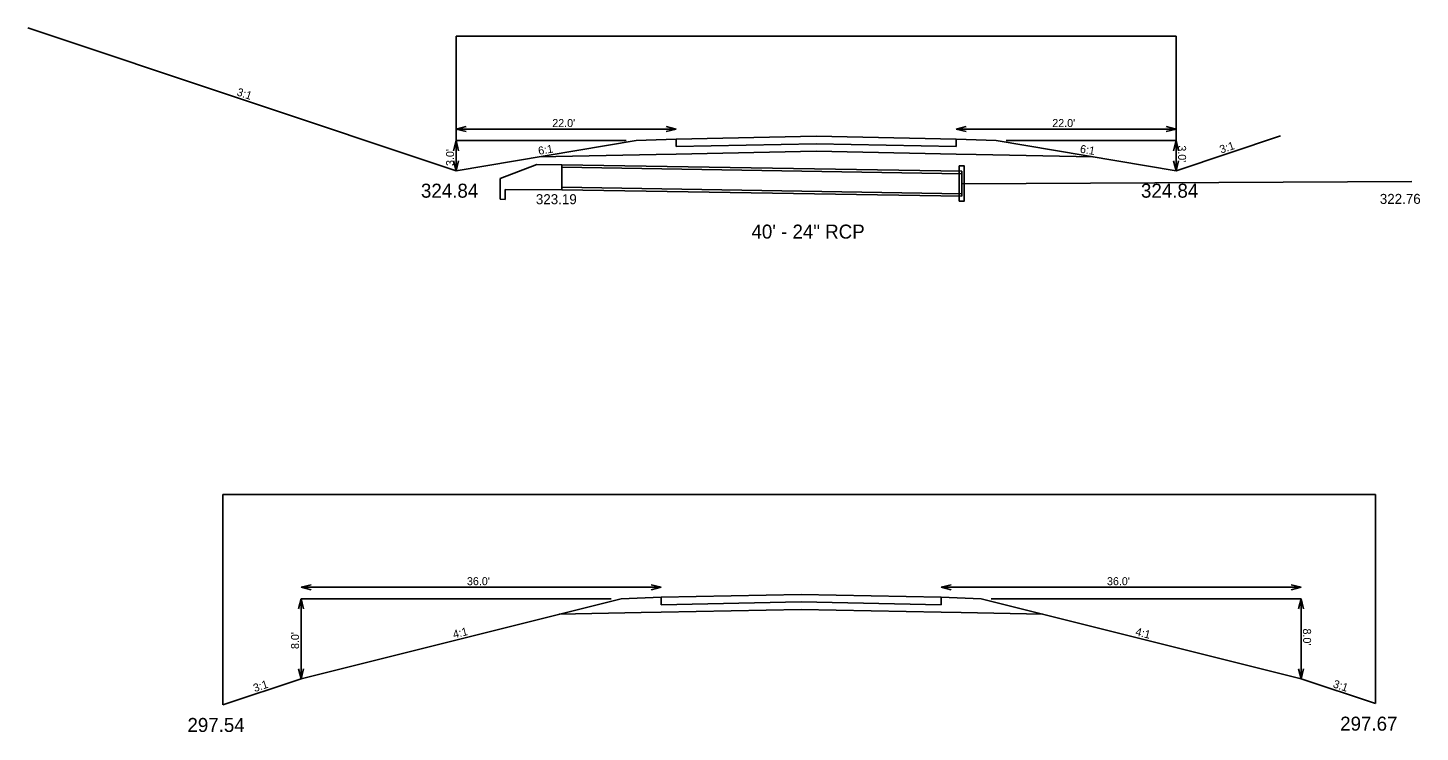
# Model space of a CAD drawing. Extents: x 2432865 to 2441203, y 1814550 to 1826842.
# Drawn here: x 2441063.6 to 2441202.8, y 1815393.3 to 1815463.7 of the extents above; entities that cross this region are included whole.
import ezdxf

# ---------------------------------------------------------------- set-up
doc = ezdxf.new("R2010")
doc.units = 0
for name, color, linetype in [('Default', 7, 'Continuous'), ('X_DRAINAGE_PIPES', 7, 'Continuous'), ('XS_M_DITCH', 7, 'Continuous'), ('XS_P_DRAINAGE', 7, 'Continuous'), ('XS_P_FINISHED_GRADE', 7, 'Continuous'), ('XS_P_SUBGRADE_GRANULAR', 7, 'Continuous'), ('XS_P_SUBGRADE_PAVEMENT', 7, 'Continuous'), ('XS_P_TX_CLEARZONE', 7, 'Continuous'), ('XS_P_TX_DCH', 7, 'Continuous'), ('XS_P_TX_FS_BS', 7, 'Continuous')]:
    doc.layers.add(name, color=color, linetype=linetype)

msp = doc.modelspace()

# ---------------------------------------------------------------- linework, layer by layer
at = {"layer": 'X_DRAINAGE_PIPES'}
msp.add_line((2441201.95, 1815448.31), (2441156.93, 1815448.09), dxfattribs=at)
at = {"layer": 'XS_M_DITCH'}
for p, q in [((2441106.37, 1815449.39), (2441106.37, 1815462.83)), ((2441106.37, 1815462.83), (2441178.37, 1815462.83)), ((2441106.37, 1815449.39), (2441106.37, 1815462.83)), ((2441106.37, 1815462.83), (2441178.37, 1815462.83)), ((2441178.37, 1815462.83), (2441178.37, 1815449.39)), ((2441178.37, 1815462.83), (2441178.37, 1815449.39)), ((2441083.04, 1815395.99), (2441083.04, 1815417.04)), ((2441083.04, 1815417.04), (2441198.3, 1815417.04)), ((2441083.04, 1815395.99), (2441083.04, 1815417.04)), ((2441083.04, 1815417.04), (2441198.3, 1815417.04)), ((2441198.3, 1815417.04), (2441198.3, 1815396.12)), ((2441198.3, 1815417.04), (2441198.3, 1815396.12))]:
    msp.add_line(p, q, dxfattribs=at)
at = {"layer": 'XS_P_DRAINAGE'}
for p, q in [((2441110.78, 1815448.61), (2441114.45, 1815450.01)), ((2441114.45, 1815450.01), (2441116.95, 1815449.99)), ((2441116.95, 1815449.99), (2441116.94, 1815447.49)), ((2441116.95, 1815449.99), (2441116.94, 1815447.49)), ((2441116.95, 1815449.99), (2441156.95, 1815449.34)), ((2441116.95, 1815449.74), (2441156.94, 1815449.09)), ((2441156.95, 1815449.34), (2441156.94, 1815446.84)), ((2441110.77, 1815446.53), (2441110.78, 1815448.61)), ((2441116.94, 1815447.74), (2441156.94, 1815447.09)), ((2441111.27, 1815446.52), (2441110.77, 1815446.53)), ((2441116.94, 1815447.49), (2441111.27, 1815447.52)), ((2441111.27, 1815447.52), (2441111.27, 1815446.52)), ((2441116.94, 1815447.49), (2441156.94, 1815446.84))]:
    msp.add_line(p, q, dxfattribs=at)
msp.add_lwpolyline([(2441156.68, 1815449.86), (2441157.18, 1815449.86), (2441157.18, 1815446.35), (2441156.68, 1815446.35)], close=True, dxfattribs=at)
at = {"layer": 'XS_P_FINISHED_GRADE'}
for p, q in [((2441106.37, 1815449.39), (2441063.55, 1815463.66)), ((2441106.37, 1815449.39), (2441063.55, 1815463.66)), ((2441124.37, 1815452.39), (2441106.37, 1815449.39)), ((2441124.37, 1815452.39), (2441106.37, 1815449.39)), ((2441128.37, 1815452.55), (2441124.37, 1815452.39)), ((2441128.37, 1815452.55), (2441124.37, 1815452.39)), ((2441128.37, 1815452.55), (2441142.37, 1815452.83)), ((2441128.37, 1815452.55), (2441142.37, 1815452.83)), ((2441142.37, 1815452.83), (2441156.37, 1815452.55)), ((2441142.37, 1815452.83), (2441156.37, 1815452.55)), ((2441156.37, 1815452.55), (2441160.37, 1815452.39)), ((2441156.37, 1815452.55), (2441160.37, 1815452.39)), ((2441160.37, 1815452.39), (2441178.37, 1815449.39)), ((2441160.37, 1815452.39), (2441178.37, 1815449.39)), ((2441178.37, 1815449.39), (2441188.81, 1815452.87)), ((2441178.37, 1815449.39), (2441188.81, 1815452.87)), ((2441122.87, 1815406.6), (2441090.87, 1815398.6)), ((2441122.87, 1815406.6), (2441090.87, 1815398.6)), ((2441126.87, 1815406.76), (2441122.87, 1815406.6)), ((2441126.87, 1815406.76), (2441122.87, 1815406.6)), ((2441126.87, 1815406.76), (2441140.87, 1815407.04)), ((2441126.87, 1815406.76), (2441140.87, 1815407.04)), ((2441140.87, 1815407.04), (2441154.87, 1815406.76)), ((2441140.87, 1815407.04), (2441154.87, 1815406.76)), ((2441154.87, 1815406.76), (2441158.87, 1815406.6)), ((2441154.87, 1815406.76), (2441158.87, 1815406.6)), ((2441158.87, 1815406.6), (2441190.87, 1815398.6)), ((2441158.87, 1815406.6), (2441190.87, 1815398.6)), ((2441090.87, 1815398.6), (2441083.04, 1815395.99)), ((2441090.87, 1815398.6), (2441083.04, 1815395.99)), ((2441190.87, 1815398.6), (2441198.3, 1815396.12)), ((2441190.87, 1815398.6), (2441198.3, 1815396.12))]:
    msp.add_line(p, q, dxfattribs=at)
at = {"layer": 'XS_P_SUBGRADE_GRANULAR'}
for p, q in [((2441126.37, 1815451.01), (2441114.69, 1815450.78)), ((2441126.37, 1815451.01), (2441114.69, 1815450.78)), ((2441128.37, 1815451.05), (2441126.37, 1815451.01)), ((2441128.37, 1815451.05), (2441126.37, 1815451.01)), ((2441128.37, 1815451.05), (2441142.37, 1815451.33)), ((2441128.37, 1815451.05), (2441142.37, 1815451.33)), ((2441142.37, 1815451.33), (2441156.37, 1815451.05)), ((2441142.37, 1815451.33), (2441156.37, 1815451.05)), ((2441156.37, 1815451.05), (2441158.37, 1815451.01)), ((2441156.37, 1815451.05), (2441158.37, 1815451.01)), ((2441158.37, 1815451.01), (2441170.06, 1815450.78)), ((2441158.37, 1815451.01), (2441170.06, 1815450.78)), ((2441124.87, 1815405.22), (2441116.69, 1815405.06)), ((2441124.87, 1815405.22), (2441116.69, 1815405.06)), ((2441126.87, 1815405.26), (2441124.87, 1815405.22)), ((2441126.87, 1815405.26), (2441124.87, 1815405.22)), ((2441126.87, 1815405.26), (2441140.87, 1815405.54)), ((2441126.87, 1815405.26), (2441140.87, 1815405.54)), ((2441140.87, 1815405.54), (2441154.87, 1815405.26)), ((2441140.87, 1815405.54), (2441154.87, 1815405.26)), ((2441154.87, 1815405.26), (2441156.87, 1815405.22)), ((2441154.87, 1815405.26), (2441156.87, 1815405.22)), ((2441156.87, 1815405.22), (2441165.04, 1815405.06)), ((2441156.87, 1815405.22), (2441165.04, 1815405.06))]:
    msp.add_line(p, q, dxfattribs=at)
at = {"layer": 'XS_P_SUBGRADE_PAVEMENT'}
for p, q in [((2441128.37, 1815451.8), (2441128.37, 1815452.55)), ((2441128.37, 1815451.8), (2441128.37, 1815452.55)), ((2441128.37, 1815451.8), (2441142.37, 1815452.08)), ((2441128.37, 1815451.8), (2441142.37, 1815452.08)), ((2441142.37, 1815452.08), (2441156.37, 1815451.8)), ((2441142.37, 1815452.08), (2441156.37, 1815451.8)), ((2441156.37, 1815451.8), (2441156.37, 1815452.55)), ((2441156.37, 1815451.8), (2441156.37, 1815452.55)), ((2441126.87, 1815406.01), (2441126.87, 1815406.76)), ((2441126.87, 1815406.01), (2441126.87, 1815406.76)), ((2441126.87, 1815406.01), (2441140.87, 1815406.29)), ((2441126.87, 1815406.01), (2441140.87, 1815406.29)), ((2441140.87, 1815406.29), (2441154.87, 1815406.01)), ((2441140.87, 1815406.29), (2441154.87, 1815406.01)), ((2441154.87, 1815406.01), (2441154.87, 1815406.76)), ((2441154.87, 1815406.01), (2441154.87, 1815406.76))]:
    msp.add_line(p, q, dxfattribs=at)
at = {"layer": 'XS_P_TX_CLEARZONE'}
for p, q in [((2441106.37, 1815453.55), (2441107.37, 1815453.8)), ((2441106.37, 1815453.55), (2441107.37, 1815453.8)), ((2441106.37, 1815453.55), (2441107.37, 1815453.3)), ((2441128.37, 1815453.55), (2441106.37, 1815453.55)), ((2441106.37, 1815453.55), (2441107.37, 1815453.3)), ((2441128.37, 1815453.55), (2441106.37, 1815453.55)), ((2441128.37, 1815453.55), (2441127.37, 1815453.8)), ((2441128.37, 1815453.55), (2441127.37, 1815453.8)), ((2441128.37, 1815453.55), (2441127.37, 1815453.3)), ((2441128.37, 1815453.55), (2441127.37, 1815453.3)), ((2441156.37, 1815453.55), (2441157.37, 1815453.8)), ((2441156.37, 1815453.55), (2441157.37, 1815453.8)), ((2441156.37, 1815453.55), (2441157.37, 1815453.3)), ((2441156.37, 1815453.55), (2441178.37, 1815453.55)), ((2441156.37, 1815453.55), (2441157.37, 1815453.3)), ((2441156.37, 1815453.55), (2441178.37, 1815453.55)), ((2441178.37, 1815453.55), (2441177.37, 1815453.8)), ((2441178.37, 1815453.55), (2441177.37, 1815453.8)), ((2441178.37, 1815453.55), (2441177.37, 1815453.3)), ((2441178.37, 1815453.55), (2441177.37, 1815453.3)), ((2441106.37, 1815452.39), (2441106.12, 1815451.39)), ((2441106.37, 1815452.39), (2441106.12, 1815451.39)), ((2441106.37, 1815452.39), (2441106.62, 1815451.39)), ((2441106.37, 1815452.39), (2441106.37, 1815449.39)), ((2441123.37, 1815452.39), (2441106.37, 1815452.39)), ((2441106.37, 1815452.39), (2441106.62, 1815451.39)), ((2441106.37, 1815452.39), (2441106.37, 1815449.39)), ((2441123.37, 1815452.39), (2441106.37, 1815452.39)), ((2441161.37, 1815452.39), (2441178.37, 1815452.39)), ((2441161.37, 1815452.39), (2441178.37, 1815452.39)), ((2441178.37, 1815452.39), (2441178.12, 1815451.39)), ((2441178.37, 1815452.39), (2441178.12, 1815451.39)), ((2441178.37, 1815452.39), (2441178.37, 1815449.39)), ((2441178.37, 1815452.39), (2441178.62, 1815451.39)), ((2441178.37, 1815452.39), (2441178.37, 1815449.39)), ((2441178.37, 1815452.39), (2441178.62, 1815451.39)), ((2441106.37, 1815449.39), (2441106.12, 1815450.39)), ((2441106.37, 1815449.39), (2441106.12, 1815450.39)), ((2441106.37, 1815449.39), (2441106.62, 1815450.39)), ((2441106.37, 1815449.39), (2441106.62, 1815450.39)), ((2441178.37, 1815449.39), (2441178.12, 1815450.39)), ((2441178.37, 1815449.39), (2441178.12, 1815450.39)), ((2441178.37, 1815449.39), (2441178.62, 1815450.39)), ((2441178.37, 1815449.39), (2441178.62, 1815450.39)), ((2441090.87, 1815407.76), (2441091.87, 1815408.01)), ((2441090.87, 1815407.76), (2441091.87, 1815408.01)), ((2441090.87, 1815407.76), (2441091.87, 1815407.51)), ((2441126.87, 1815407.76), (2441090.87, 1815407.76)), ((2441090.87, 1815407.76), (2441091.87, 1815407.51)), ((2441126.87, 1815407.76), (2441090.87, 1815407.76)), ((2441126.87, 1815407.76), (2441125.87, 1815408.01)), ((2441126.87, 1815407.76), (2441125.87, 1815408.01)), ((2441126.87, 1815407.76), (2441125.87, 1815407.51)), ((2441126.87, 1815407.76), (2441125.87, 1815407.51)), ((2441154.87, 1815407.76), (2441155.87, 1815408.01)), ((2441154.87, 1815407.76), (2441155.87, 1815408.01)), ((2441154.87, 1815407.76), (2441155.87, 1815407.51)), ((2441154.87, 1815407.76), (2441190.87, 1815407.76)), ((2441154.87, 1815407.76), (2441155.87, 1815407.51)), ((2441154.87, 1815407.76), (2441190.87, 1815407.76)), ((2441190.87, 1815407.76), (2441189.87, 1815408.01)), ((2441190.87, 1815407.76), (2441189.87, 1815408.01)), ((2441190.87, 1815407.76), (2441189.87, 1815407.51)), ((2441190.87, 1815407.76), (2441189.87, 1815407.51)), ((2441090.87, 1815406.6), (2441090.62, 1815405.6)), ((2441090.87, 1815406.6), (2441090.62, 1815405.6)), ((2441090.87, 1815406.6), (2441091.12, 1815405.6)), ((2441090.87, 1815406.6), (2441090.87, 1815398.6)), ((2441121.87, 1815406.6), (2441090.87, 1815406.6)), ((2441090.87, 1815406.6), (2441091.12, 1815405.6)), ((2441090.87, 1815406.6), (2441090.87, 1815398.6)), ((2441121.87, 1815406.6), (2441090.87, 1815406.6)), ((2441159.87, 1815406.6), (2441190.87, 1815406.6)), ((2441159.87, 1815406.6), (2441190.87, 1815406.6)), ((2441190.87, 1815406.6), (2441190.62, 1815405.6)), ((2441190.87, 1815406.6), (2441190.62, 1815405.6)), ((2441190.87, 1815406.6), (2441190.87, 1815398.6)), ((2441190.87, 1815406.6), (2441191.12, 1815405.6)), ((2441190.87, 1815406.6), (2441190.87, 1815398.6)), ((2441190.87, 1815406.6), (2441191.12, 1815405.6)), ((2441090.87, 1815398.6), (2441090.62, 1815399.6)), ((2441090.87, 1815398.6), (2441090.62, 1815399.6)), ((2441090.87, 1815398.6), (2441091.12, 1815399.6)), ((2441090.87, 1815398.6), (2441091.12, 1815399.6)), ((2441190.87, 1815398.6), (2441190.62, 1815399.6)), ((2441190.87, 1815398.6), (2441190.62, 1815399.6)), ((2441190.87, 1815398.6), (2441191.12, 1815399.6)), ((2441190.87, 1815398.6), (2441191.12, 1815399.6))]:
    msp.add_line(p, q, dxfattribs=at)

# ---------------------------------------------------------------- texts
at = {"layer": 'Default'}
for s, p in [('323.19', (2441114.35, 1815446.04)), ('322.76', (2441198.74, 1815446.07))]:
    msp.add_text(s, height=1, dxfattribs=at).set_placement(p)
at = {"layer": 'XS_P_DRAINAGE'}
msp.add_text('40\' - 24" RCP', height=1.4, dxfattribs=at).set_placement((2441135.91, 1815442.6))
at = {"layer": 'XS_P_TX_CLEARZONE'}
for s, p in [("22.0'", (2441115.99, 1815453.75)), ("22.0'", (2441115.99, 1815453.75)), ("22.0'", (2441165.99, 1815453.75)), ("22.0'", (2441165.99, 1815453.75)), ("36.0'", (2441107.46, 1815407.96)), ("36.0'", (2441107.46, 1815407.96)), ("36.0'", (2441171.46, 1815407.96)), ("36.0'", (2441171.46, 1815407.96))]:
    msp.add_text(s, height=0.8, dxfattribs=at).set_placement(p)
for s, rotation, p in [("3.0'", 270, (2441178.57, 1815451.92)), ("3.0'", 270, (2441178.57, 1815451.92)), ("3.0'", 90, (2441106.17, 1815449.86)), ("3.0'", 90, (2441106.17, 1815449.86)), ("8.0'", 90, (2441090.67, 1815401.58)), ("8.0'", 90, (2441090.67, 1815401.58)), ("8.0'", 270, (2441191.07, 1815403.63)), ("8.0'", 270, (2441191.07, 1815403.63))]:
    msp.add_text(s, height=0.8, rotation=rotation, dxfattribs=at).set_placement(p)
at = {"layer": 'XS_P_TX_DCH'}
for s, p in [('324.84', (2441102.86, 1815446.69)), ('324.84', (2441102.86, 1815446.69)), ('324.84', (2441174.86, 1815446.69)), ('324.84', (2441174.86, 1815446.69)), ('297.67', (2441194.78, 1815393.42)), ('297.67', (2441194.78, 1815393.42)), ('297.54', (2441079.51, 1815393.29)), ('297.54', (2441079.51, 1815393.29))]:
    msp.add_text(s, height=1.4, dxfattribs=at).set_placement(p)
at = {"layer": 'XS_P_TX_FS_BS'}
for s, rotation, p in [('3:1', 341.5651, (2441084.38, 1815456.93)), ('3:1', 341.5651, (2441084.38, 1815456.93)), ('6:1', 9.4623, (2441114.65, 1815450.97)), ('6:1', 9.4623, (2441114.65, 1815450.97)), ('6:1', 350.5377, (2441168.72, 1815451.2)), ('6:1', 350.5377, (2441168.72, 1815451.2)), ('3:1', 18.4349, (2441182.88, 1815451.1)), ('3:1', 18.4349, (2441182.88, 1815451.1)), ('4:1', 14.0362, (2441106.16, 1815402.63)), ('4:1', 14.0362, (2441106.16, 1815402.63)), ('4:1', 345.9638, (2441174.25, 1815402.96)), ('4:1', 345.9638, (2441174.25, 1815402.96)), ('3:1', 18.4349, (2441086.24, 1815397.27)), ('3:1', 18.4349, (2441086.24, 1815397.27)), ('3:1', 341.5651, (2441194, 1815397.77)), ('3:1', 341.5651, (2441194, 1815397.77))]:
    msp.add_text(s, height=0.8, rotation=rotation, dxfattribs=at).set_placement(p)

doc.saveas('drawing.dxf')
